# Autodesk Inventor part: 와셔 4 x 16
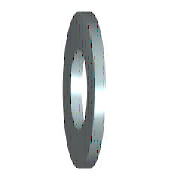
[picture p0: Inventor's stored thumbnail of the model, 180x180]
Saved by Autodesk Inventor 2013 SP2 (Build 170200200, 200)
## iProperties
IsCustomPart: 1
Created: 2012-02
Part Number: 와셔 4 x 16
Material: 강철, 연강
Description: 미터법 평면 와셔
Document SubType Name: Modeling
Standard: ANSI B18.22M
Designer: mduedu
Standard Revision: 1999
Standards Organization: ANSI
Language: ko-KR
Size Designation: 4 W
Categories: <MemberInstance><Categories><Category DisplayName="조임쇠" InternalName="e4da775c-781d-43d5-af7c-5136215cf5a6" Mnemonic="FSTN"><Category DisplayName="와셔" InternalN
Density: 1 g/cm^3
Author: mduedu
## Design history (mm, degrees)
sketch "스케치"
  geometry: C1 r 8 at (0, 0); C2 r 2.35 at (0, 0); 1 further point
  constraints: 2 centre point, 2 coincident
  dimensions: "d0" = 4.7 diameter of C2 (= SD1); "d1" = 16 diameter of C1 (= SD2)
extrude "본체" new body sketch "스케치" distance "d2" = 2.3 (= SD); taper "d3" = 0 deg
workaxis "Work Axis1"
workplane "Work Plane1"
body "Solid1"
other parameters: "SD1" = 4.7 [user parameter; used in 1 equation term], "SD2" = 16 [user parameter; used in 1 equation term], "SD" = 2.3 [user parameter; used in 1 equation term], "d4" = 0, "d5" = 0, "d6" = 0, "d7" = 0, "NND" = 4 [user parameter]
